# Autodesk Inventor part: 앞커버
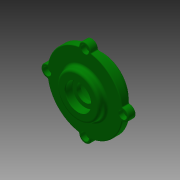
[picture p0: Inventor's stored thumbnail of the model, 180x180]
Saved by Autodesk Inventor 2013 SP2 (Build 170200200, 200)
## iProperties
Created: 2016-05
Part Number: 앞커버
Document SubType Name: Modeling
Designer: mduedu
Density: 2.71 g/cm^3
Material: 알루미늄 6061
Author: mduedu
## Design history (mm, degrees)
sketch "스케치1"
  geometry: C1 r 32 at (0, 0); C2 r 44 at (0, 0); 1 further point
  constraints: 2 centre point, 2 coincident
  dimensions: "d33" = 88 diameter of C2; "d34" = 64 diameter of C1
extrude "돌출1" new body sketch "스케치1" distance "d0" = 8; taper "d1" = 0 deg
extrude "돌출2" join sketch "스케치1" distance "d2" = 8; taper "d3" = 0 deg; dims "d35" = 12, "d36" = 0
sketch "스케치6"
  geometry: C1 r 25 at (0, 0); 2 further points
  constraints: 2 coincident, 1 centre point
  dimensions: "d42" = 50 diameter of C1
extrude "돌출4" join sketch "스케치6" distance "d43" = 8; taper "d44" = 0 deg
sketch "스케치9"
  geometry: C1 r 7 at (0, 44); 2 further points
  constraints: 2 vertical alignment, 1 centre point, 1 other
  dimensions: "d70" = 14 diameter of C1
extrude "돌출5" join sketch "스케치9" stored distance "d71" = 10; taper "d72" = 0 deg
fillet "모깎기9" dims "d76" = 1
sketch "스케치10"
  geometry: C1 r 25 at (0, 0) reference; A1 r 1 centre (-44.284, 7.995) between (-44.249, 6.996) and (-43.3, 7.817) reference; A2 r 7 centre (-44, 0) between (-44.249, 6.996) and (-44.249, -6.996) reference; A3 r 1 centre (-44.284, -7.995) between (-43.3, -7.817) and (-44.249, -6.996) reference; A4 r 44 centre (0, 0) between (-43.3, -7.817) and (-7.817, -43.3) reference; A5 r 1 centre (-7.995, -44.284) between (-6.996, -44.249) and (-7.817, -43.3) reference; A6 r 7 centre (0, -44) between (-6.996, -44.249) and (6.996, -44.249) reference; A7 r 1 centre (7.995, -44.284) between (7.817, -43.3) and (6.996, -44.249) reference; A8 r 1 centre (7.995, 44.284) between (6.996, 44.249) and (7.817, 43.3) reference; A9 r 7 centre (0, 44) between (6.996, 44.249) and (-6.996, 44.249) reference; A10 r 1 centre (-7.995, 44.284) between (-7.817, 43.3) and (-6.996, 44.249) reference; A11 r 7 centre (44, 0) between (44.249, -6.996) and (44.249, 6.996) reference; A12 r 44 centre (0, 0) between (-7.817, 43.3) and (-43.3, 7.817) reference; A13 r 44 centre (0, 0) between (7.817, -43.3) and (43.3, -7.817) reference; A14 r 1 centre (44.284, -7.995) between (44.249, -6.996) and (43.3, -7.817) reference; A15 r 1 centre (44.284, 7.995) between (43.3, 7.817) and (44.249, 6.996) reference; A16 r 44 centre (0, 0) between (43.3, 7.817) and (7.817, 43.3) reference; 4 further points
  constraints: 3 coincident
hole "구멍3" sketch "스케치10" at (0, 44), (-44, 0), (0, -44), (44, 0) diameter "d77" = 5.5; stored, may be unused: countersink angle "d81" = 90 deg, drill point angle "d83" = 118 deg; dims "d78" = 6, "d79" = 9.5, "d80" = 5.4, "d82" = 8
fillet "모깎기10" dims "d84" = 1
fillet "모깎기7" dims "d68" = 3
fillet "모깎기8" dims "d69" = 3
sketch "스케치4"
  geometry: L1 (0, -12)-(0, 16); L2 (-20, -12)-(-20, 0); L3 (-20, 0)-(-15, 0); L4 (-15, 0)-(-15, 3); L5 (-15, 3)-(-10, 3); L6 (-10, 3)-(-10, 7.7); L7 (-10, 7.7)-(-15, 7.7); L8 (-15, 7.7)-(-15, 16); L9 (32, -12)-(-32, -12) reference; L10 (25, 16)-(-25, 16) reference; 1 further point
  constraints: 16 end point, 6 parallel, 3 point on line, 2 midpoint, 1 perpendicular, 1 vertical
  dimensions: "d15" = 40 diameter of L2 L1; "d16" = 30 diameter of L8 L1; "d18" = 12 distance of L2.start L2.end; "d19" = 3 distance of L3.end L4.end; "d20" = 30 diameter of L4 L1; "d21" = 20 diameter of L6 L1; "d45" = 8.3 distance of L7.end L8.end
revolve "회전1" sketch "스케치4" stored, may be unused: angle "d22" = 90 deg
fillet "모깎기2" dims "d23" = 3
fillet "모깎기3" dims "d24" = 0.3
chamfer "모따기2" distance "d46" = 1; stored, may be unused: second distance "d47" = 2, angle "d48" = 45 deg
chamfer "모따기3" distance "d64" = 0.8; stored, may be unused: second distance "d65" = 2, angle "d66" = 30 deg
node "솔리드1"
pattern_circular "원형 패턴1" dims angle "d74" = 360 deg
node "투영된 루프1"
